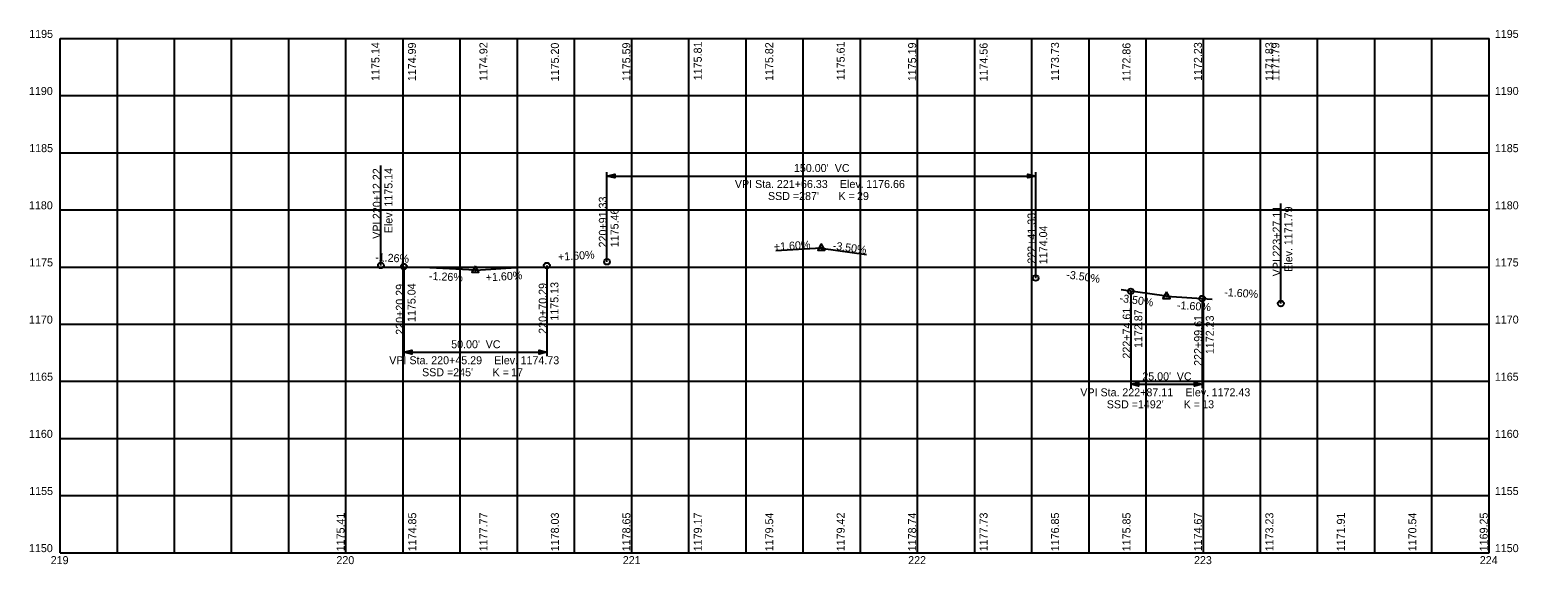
# Model space of a CAD drawing. Extents: x -111 to 410, y 1146 to 1333.
import ezdxf

# ---------------------------------------------------------------- set-up
doc = ezdxf.new("R2010")
doc.units = 0
for name, color, linetype in [('PF_P_Sta_Elev_Text', 7, 'Continuous'), ('PF_P_Text', 7, 'Continuous'), ('PF_P_Text_Curve', 7, 'Continuous'), ('PF_P_Text_Grade', 7, 'Continuous'), ('PF_P_Text_Points', 7, 'Continuous'), ('PF_P_Text_Strip_Grades_20', 7, 'Continuous'), ('PF_X_Text_Strip_Grade', 7, 'Continuous'), ('SH_Major_Grid_Line', 7, 'Continuous')]:
    doc.layers.add(name, color=color, linetype=linetype)

msp = doc.modelspace()

# ---------------------------------------------------------------- linework, layer by layer
at = {"layer": 'PF_P_Text'}
for points in [[(166.33, 1258.09), (165.08, 1255.93), (167.58, 1255.93)], [(45.29, 1250.35), (44.04, 1248.18), (46.54, 1248.18)], [(287.11, 1241.18), (285.86, 1239.02), (288.36, 1239.02)]]:
    msp.add_lwpolyline(points, close=True, dxfattribs=at)
at = {"layer": 'PF_P_Text_Curve'}
for p, q in [((91.33, 1251.85), (91.33, 1283.25)), ((91.33, 1281.95), (91.33, 1281.75)), ((91.33, 1281.85), (241.33, 1281.85)), ((241.33, 1246.15), (241.33, 1283.25)), ((241.33, 1281.75), (241.33, 1281.95)), ((20.29, 1250.16), (20.29, 1218.76)), ((70.29, 1250.5), (70.29, 1218.76)), ((274.61, 1241.49), (274.61, 1207.54)), ((299.61, 1238.94), (299.61, 1207.54)), ((20.29, 1220.26), (20.29, 1220.06)), ((20.29, 1220.16), (70.29, 1220.16)), ((70.29, 1220.06), (70.29, 1220.26)), ((274.61, 1209.04), (274.61, 1208.84)), ((274.61, 1208.94), (299.61, 1208.94)), ((299.61, 1208.84), (299.61, 1209.04))]:
    msp.add_line(p, q, dxfattribs=at)
for points in [[(91.33, 1281.85), (94.04, 1282.53), (94.04, 1281.17)], [(241.33, 1281.85), (238.61, 1281.17), (238.61, 1282.53)], [(20.29, 1220.16), (23.01, 1220.84), (23.01, 1219.48)], [(70.29, 1220.16), (67.57, 1219.48), (67.57, 1220.84)], [(274.61, 1208.94), (277.33, 1209.62), (277.33, 1208.26)], [(299.61, 1208.94), (296.89, 1208.26), (296.89, 1209.62)]]:
    msp.add_lwpolyline(points, close=True, dxfattribs=at)
for centre in [(20.29, 1250.16), (70.29, 1250.5), (91.33, 1251.85), (241.33, 1246.15), (274.61, 1241.49), (299.61, 1238.94)]:
    msp.add_circle(centre, 1, dxfattribs=at)
at = {"layer": 'PF_P_Text_Grade'}
for p, q in [((166.33, 1256.65), (150.36, 1255.63)), ((166.33, 1256.65), (166.33, 1256.65)), ((166.33, 1256.65), (182.17, 1254.43)), ((45.29, 1248.9), (29.31, 1249.71)), ((45.29, 1248.9), (61.26, 1249.93)), ((45.29, 1248.9), (45.29, 1248.9)), ((287.11, 1239.74), (271.26, 1241.96)), ((287.11, 1239.74), (287.11, 1239.74)), ((287.11, 1239.74), (303.08, 1238.72))]:
    msp.add_line(p, q, dxfattribs=at)
for centre in [(166.33, 1256.65), (166.33, 1256.65), (45.29, 1248.9), (45.29, 1248.9), (287.11, 1239.74), (287.11, 1239.74)]:
    msp.add_circle(centre, 0.1, dxfattribs=at)
at = {"layer": 'PF_P_Text_Points'}
for p, q in [((12.22, 1250.57), (12.22, 1285.57)), ((327.11, 1237.18), (327.11, 1272.18))]:
    msp.add_line(p, q, dxfattribs=at)
for centre in [(12.22, 1250.57), (327.11, 1237.18)]:
    msp.add_circle(centre, 1, dxfattribs=at)
at = {"layer": 'SH_Major_Grid_Line'}
for p, q in [((-100, 1330), (400, 1330)), ((-100, 1150), (-100, 1330)), ((-100, 1150), (-100, 1330)), ((-80, 1150), (-80, 1330)), ((-60, 1150), (-60, 1330)), ((-40, 1150), (-40, 1330)), ((-20, 1150), (-20, 1330)), ((0, 1150), (0, 1330)), ((20, 1150), (20, 1330)), ((40, 1150), (40, 1330)), ((60, 1150), (60, 1330)), ((80, 1150), (80, 1330)), ((100, 1150), (100, 1330)), ((120, 1150), (120, 1330)), ((140, 1150), (140, 1330)), ((160, 1150), (160, 1330)), ((180, 1150), (180, 1330)), ((200, 1150), (200, 1330)), ((220, 1150), (220, 1330)), ((240, 1150), (240, 1330)), ((260, 1150), (260, 1330)), ((280, 1150), (280, 1330)), ((300, 1150), (300, 1330)), ((320, 1150), (320, 1330)), ((340, 1150), (340, 1330)), ((360, 1150), (360, 1330)), ((380, 1150), (380, 1330)), ((400, 1150), (400, 1330)), ((-100, 1310), (400, 1310)), ((-100, 1290), (400, 1290)), ((-100, 1270), (400, 1270)), ((-100, 1250), (400, 1250)), ((-100, 1230), (400, 1230)), ((-100, 1210), (400, 1210)), ((-100, 1190), (400, 1190)), ((-100, 1170), (400, 1170)), ((-100, 1150), (400, 1150))]:
    msp.add_line(p, q, dxfattribs=at)

# ---------------------------------------------------------------- texts
at = {"layer": 'PF_P_Sta_Elev_Text'}
for s, p in [('1195', (-110.84, 1330.2)), ('1195', (402, 1330.2)), ('1190', (-110.93, 1310.2)), ('1190', (402, 1310.2)), ('1185', (-110.84, 1290.2)), ('1185', (402, 1290.2)), ('1180', (-110.93, 1270.2)), ('1180', (402, 1270.2)), ('1175', (-110.84, 1250.2)), ('1175', (402, 1250.2)), ('1170', (-110.93, 1230.2)), ('1170', (402, 1230.2)), ('1165', (-110.84, 1210.2)), ('1165', (402, 1210.2)), ('1160', (-110.93, 1190.2)), ('1160', (402, 1190.2)), ('1155', (-110.84, 1170.2)), ('1155', (402, 1170.2)), ('1150', (-110.93, 1150.2)), ('1150', (402, 1150.2)), ('219', (-103.32, 1146)), ('220', (-3.35, 1146)), ('221', (96.85, 1146)), ('222', (196.72, 1146)), ('223', (296.73, 1146)), ('224', (396.73, 1146))]:
    msp.add_text(s, height=2.8, dxfattribs=at).set_placement(p)
at = {"layer": 'PF_P_Text_Curve'}
for s, p in [("150.00'", (156.73, 1283.25)), (' VC', (169.99, 1283.25)), ('VPI Sta. ', (136.08, 1277.65)), ('SSD = ', (147.66, 1273.45)), ('221+66.33', (150.77, 1277.65)), ("287'", (158.55, 1273.45)), ('K = ', (172.33, 1273.45)), ('   Elev. ', (169.72, 1277.65)), ('29', (178.81, 1273.45)), ('1176.66', (182.03, 1277.65)), ("50.00'", (36.81, 1221.56)), (' VC', (47.84, 1221.56)), ('VPI Sta. ', (15.13, 1215.96)), ('220+45.29', (29.82, 1215.96)), ('   Elev. ', (48.77, 1215.96)), ('1174.73', (61.08, 1215.96)), ('SSD = ', (26.62, 1211.76)), ("245'", (37.51, 1211.76)), ('K = ', (51.29, 1211.76)), ('17', (57.77, 1211.76)), ("25.00'", (278.63, 1210.34)), (' VC', (289.66, 1210.34)), ('VPI Sta. ', (256.95, 1204.74)), ('SSD = ', (266.21, 1200.54)), ('222+87.11', (271.64, 1204.74)), ("1492'", (277.1, 1200.54)), ('K = ', (293.11, 1200.54)), ('   Elev. ', (290.59, 1204.74)), ('13', (299.59, 1200.54)), ('1172.43', (302.9, 1204.74))]:
    msp.add_text(s, height=2.8, dxfattribs=at).set_placement(p)
at = {"layer": 'PF_P_Text_Grade'}
for s, rotation, p in [('+1.60%', 3.6619, (74.27, 1252.16)), ('+1.60%', 3.6619, (149.81, 1255.67)), ('-3.50%', 352.0304, (170.18, 1256.19)), ('-1.26%', 357.1147, (10.14, 1252.07)), ('-1.26%', 357.1147, (28.98, 1245.52)), ('+1.60%', 3.6619, (49, 1244.93)), ('-3.50%', 352.0304, (251.9, 1246.07)), ('-3.50%', 352.0304, (270.56, 1237.82)), ('-1.60%', 356.3381, (307.25, 1239.85)), ('-1.60%', 356.3381, (290.71, 1235.3))]:
    msp.add_text(s, height=2.8, rotation=rotation, dxfattribs=at).set_placement(p)
at = {"layer": 'PF_P_Text_Points'}
for s, p in [('220+12.22', (12.18, 1266.76)), ('1175.14', (16.27, 1271.14)), ('220+91.33', (91.28, 1256.85)), ('223+27.11', (327.07, 1253.63)), ('1171.79', (331.16, 1257.64)), ('Elev. ', (16.27, 1261.82)), ('1175.46', (95.37, 1256.93)), ('222+41.33', (241.28, 1251.15)), ('VPI ', (12.18, 1259.87)), ('1174.04', (245.36, 1250.98)), ('Elev. ', (331.16, 1248.32)), ('VPI ', (327.07, 1246.74)), ('220+20.29', (20.25, 1226.27)), ('1175.04', (24.34, 1230.74)), ('220+70.29', (70.25, 1226.61)), ('1175.13', (74.34, 1231.22)), ('222+74.61', (274.57, 1217.94)), ('1172.87', (278.65, 1221.66)), ('222+99.61', (299.57, 1215.39)), ('1172.23', (303.66, 1219.5))]:
    msp.add_text(s, height=2.8, rotation=90, dxfattribs=at).set_placement(p)
at = {"layer": 'PF_P_Text_Strip_Grades_20'}
for s, p in [('1175.14', (11.72, 1315.14)), ('1174.99', (24.5, 1315.04)), ('1174.92', (49.5, 1315.12)), ('1175.20', (74.5, 1314.99)), ('1175.59', (99.5, 1315.04)), ('1175.81', (124.5, 1315.38)), ('1175.82', (149.5, 1315.12)), ('1175.61', (174.5, 1315.38)), ('1175.19', (199.5, 1315.04)), ('1174.56', (224.5, 1314.96)), ('1173.73', (249.5, 1315.14)), ('1172.86', (274.5, 1314.96)), ('1172.23', (299.5, 1315.14)), ('1171.83', (324.5, 1315.14)), ('1171.79', (326.61, 1315.04))]:
    msp.add_text(s, height=2.8, rotation=90, dxfattribs=at).set_placement(p)
at = {"layer": 'PF_X_Text_Strip_Grade'}
for s, p in [('1175.41', (-0.5, 1150.5)), ('1174.85', (24.58, 1150.5)), ('1177.77', (49.5, 1150.5)), ('1178.03', (74.5, 1150.5)), ('1178.65', (99.5, 1150.5)), ('1179.17', (124.5, 1150.5)), ('1179.54', (149.5, 1150.5)), ('1179.42', (174.5, 1150.5)), ('1178.74', (199.5, 1150.5)), ('1177.73', (224.5, 1150.5)), ('1176.85', (249.51, 1150.5)), ('1175.85', (274.51, 1150.5)), ('1174.67', (299.51, 1150.5)), ('1173.23', (324.51, 1150.5)), ('1171.91', (349.51, 1150.5)), ('1170.54', (374.52, 1150.5)), ('1169.25', (399.51, 1150.5))]:
    msp.add_text(s, height=2.8, rotation=90, dxfattribs=at).set_placement(p)

doc.saveas('drawing.dxf')
